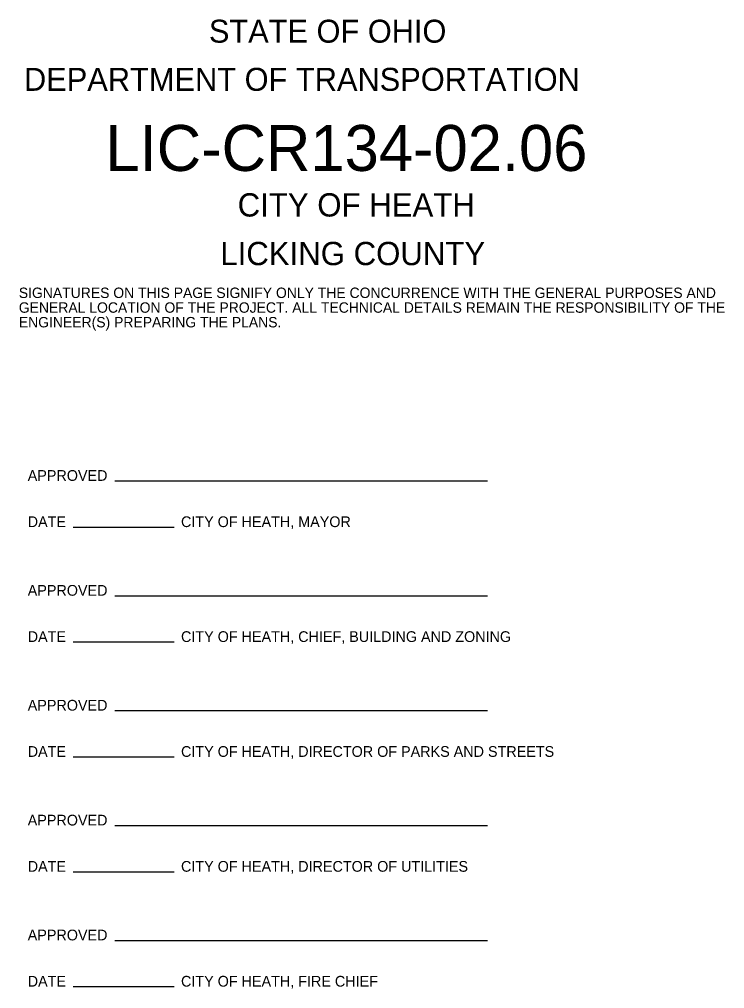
# Model space of a CAD drawing. Extents: x -38.3 to 52.8, y 6.3 to 33.6.
# Drawn here: x -38.31 to -30.95, y 6.31 to 16.43 of the extents above; entities that cross this region are included whole.
import ezdxf

# ---------------------------------------------------------------- set-up
doc = ezdxf.new("R2010")
doc.units = 0
doc.layers.add('SH_Data', color=7, linetype='Continuous')
doc.layers.add('SH_Text', color=7, linetype='Continuous')

msp = doc.modelspace()

# ---------------------------------------------------------------- linework, layer by layer
at = {"layer": 'SH_Data'}
for p, q in [((-37.311, 11.61), (-33.419, 11.61)), ((-37.746, 11.127), (-36.692, 11.127)), ((-37.311, 10.41), (-33.419, 10.41)), ((-37.746, 9.927), (-36.692, 9.927)), ((-37.311, 9.21), (-33.419, 9.21)), ((-37.746, 8.727), (-36.692, 8.727)), ((-37.311, 8.01), (-33.419, 8.01)), ((-37.746, 7.527), (-36.692, 7.527)), ((-37.311, 6.81), (-33.419, 6.81)), ((-37.746, 6.327), (-36.692, 6.327))]:
    msp.add_line(p, q, dxfattribs=at)

# ---------------------------------------------------------------- texts
for s, height, p in [('STATE OF OHIO', 0.24, (-36.328, 16.187)), ('DEPARTMENT OF TRANSPORTATION', 0.24027, (-38.258, 15.684)), ('LIC-CR134-02.06', 0.48, (-37.408, 14.847)), ('CITY OF HEATH', 0.2432, (-36.028, 14.371)), ('LICKING COUNTY', 0.2432, (-36.209, 13.863)), ('SIGNATURES ON THIS PAGE SIGNIFY ONLY THE CONCURRENCE WITH THE GENERAL PURPOSES AND', 0.1088, (-38.312, 13.52)), ('GENERAL LOCATION OF THE PROJECT. ALL TECHNICAL DETAILS REMAIN THE RESPONSIBILITY OF THE', 0.1088, (-38.312, 13.366)), ('ENGINEER(S) PREPARING THE PLANS.', 0.1088, (-38.312, 13.213)), ('APPROVED', 0.112, (-38.219, 11.61)), ('DATE', 0.112, (-38.219, 11.127)), ('APPROVED', 0.112, (-38.219, 10.41)), ('DATE', 0.112, (-38.219, 9.927)), ('APPROVED', 0.112, (-38.219, 9.21)), ('DATE', 0.112, (-38.219, 8.727)), ('APPROVED', 0.112, (-38.219, 8.01)), ('DATE', 0.112, (-38.219, 7.527)), ('APPROVED', 0.112, (-38.219, 6.81)), ('DATE', 0.112, (-38.219, 6.327))]:
    msp.add_text(s, height=height, dxfattribs=at).set_placement(p)
at = {"layer": 'SH_Text'}
for s, p in [('CITY OF HEATH, MAYOR', (-36.619, 11.127)), ('CITY OF HEATH, CHIEF, BUILDING AND ZONING', (-36.619, 9.927)), ('CITY OF HEATH, DIRECTOR OF PARKS AND STREETS', (-36.619, 8.727)), ('CITY OF HEATH, DIRECTOR OF UTILITIES', (-36.619, 7.527)), ('CITY OF HEATH, FIRE CHIEF', (-36.619, 6.327))]:
    msp.add_text(s, height=0.112, dxfattribs=at).set_placement(p)

doc.saveas('drawing.dxf')
